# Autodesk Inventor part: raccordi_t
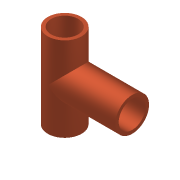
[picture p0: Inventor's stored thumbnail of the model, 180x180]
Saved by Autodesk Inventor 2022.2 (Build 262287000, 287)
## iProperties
Created: 2025-02
Part Number: raccordi_t
Material: Rame, Fuso
Document SubType Name: Modeling
Designer: 18907419
Density: 8.94 g/cm^3
Appearance: Rame - Satinato
Author: 18907419
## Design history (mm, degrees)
sketch "Schizzo1"
  geometry: C1 r 10 at (0, 0); C2 r 8 at (0, 0); 1 further point
  constraints: 2 centre point, 1 coincident
  dimensions: "d0" = 20 diameter of C1; "d1" = 2 radial gap between concentric circles of C1 C2
extrude "Estrusione1" new body sketch "Schizzo1" distance "d2" = 50; taper "d3" = 0 deg
node "Piano di lavoro2"
sketch "Schizzo2"
  geometry: C1 r 10 at (25, 0); C2 r 8 at (25, 0); 1 further point
  constraints: 2 centre point
  dimensions: "d6" = 20 diameter of C1; "d8" = 2 radial gap between concentric circles of C1 C2
extrude "Estrusione2" join sketch "Schizzo2" stored distance "d9" = 10; taper "d10" = 0 deg; dims "d0" = 20
sketch "Schizzo3"
  geometry: C1 r 8 at (0, 0) reference; 1 further point
extrude "Estrusione3" cut sketch "Schizzo3" stored distance "d11" = 10; taper "d12" = 0 deg
node "Solido1"
